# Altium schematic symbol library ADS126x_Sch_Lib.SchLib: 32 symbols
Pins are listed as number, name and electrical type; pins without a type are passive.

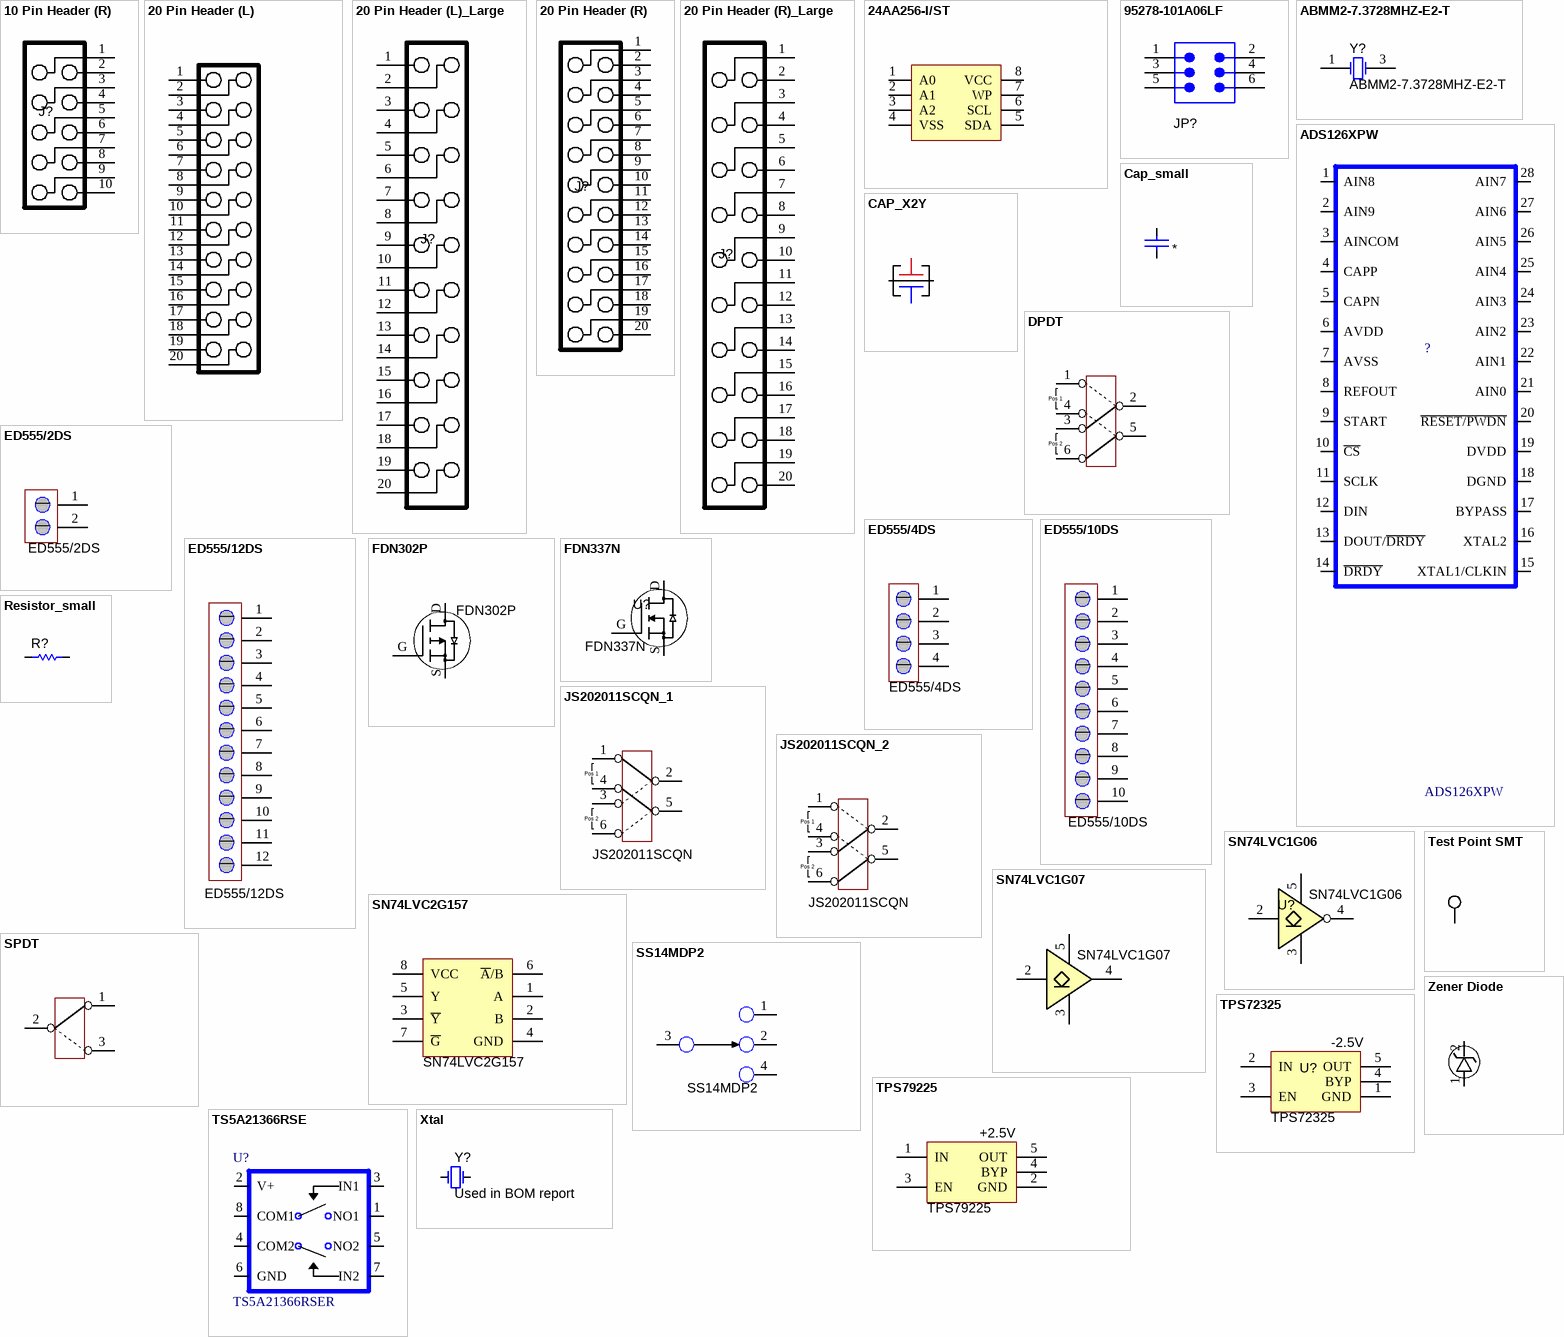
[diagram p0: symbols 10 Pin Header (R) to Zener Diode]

## 10 Pin Header (R)
designator J?, comment TSM-110-01-T-DV-P  (value not drawn)
Manufacturer: Samtec; SymbolCreator: a0282860; CompType: Used in some BOM reports.  Useful for finding later.; U/M: EA, IN, or GM
footprint HEADER_TSM-105-XX-DV_TH
pins: 1, 2, 3, 4, 5, 6, 7, 8, 9, 10

## 20 Pin Header (L)
designator J?, comment TSM-110-01-T-DV-P  (value not drawn)
Manufacturer: Samtec; SymbolCreator: a0282860; CompType: Used in some BOM reports.  Useful for finding later.; U/M: EA, IN, or GM
footprint HEADER_TSM-110-XX-DV_TH
pins: 1, 2, 3, 4, 5, 6, 7, 8, 9, 10, 11, 12, 13, 14, 15, 16, 17, 18, 19, 20

## 20 Pin Header (L)_Large
designator J?, comment TSM-110-01-T-DV-P  (value not drawn)
Manufacturer: Samtec; SymbolCreator: a0282860; CompType: Used in some BOM reports.  Useful for finding later.; U/M: EA, IN, or GM
footprint HEADER_TSM-110-XX-DV_TH
pins: 1, 2, 3, 4, 5, 6, 7, 8, 9, 10, 11, 12, 13, 14, 15, 16, 17, 18, 19, 20

## 20 Pin Header (R)
designator J?, comment TSM-110-01-T-DV-P  (value not drawn)
Manufacturer: Samtec; SymbolCreator: a0282860; CompType: Used in some BOM reports.  Useful for finding later.; U/M: EA, IN, or GM
footprint HEADER_TSM-110-XX-DV_TH
pins: 1, 2, 3, 4, 5, 6, 7, 8, 9, 10, 11, 12, 13, 14, 15, 16, 17, 18, 19, 20

## 20 Pin Header (R)_Large
designator J?, comment TSM-110-01-T-DV-P  (value not drawn)
Manufacturer: Samtec; SymbolCreator: a0282860; CompType: Used in some BOM reports.  Useful for finding later.; U/M: EA, IN, or GM
footprint HEADER_TSM-110-XX-DV_TH
pins: 1, 2, 3, 4, 5, 6, 7, 8, 9, 10, 11, 12, 13, 14, 15, 16, 17, 18, 19, 20

## 24AA256-I/ST
designator U?
IC, EEPROM, 256 kBIT, 400 kHz, 8TSSOP; Manufacturer: Microchip; SymbolCreator: a0282860; U/M: EA
pins: 1 A0, 2 A1, 3 A2, 4 VSS, 5 SDA, 6 SCL, 7 WP, 8 VCC

## 95278-101A06LF
designator JP?  (value not drawn)
Header, SMT, 100mil, 5x2; Manufacturer: FCI; U/M: EA
footprint 95278-101A06LF
pins: 1, 2, 3, 4, 5, 6

## ABMM2-7.3728MHZ-E2-T
designator Y?
Crystal, 7.3728MHz, 18pF, SMD; Manufacturer: Abracon Corportation; SymbolCreator: a0282860; U/M: EA; TaMin_C: -20; TaMax_C: 70; Frequency Stability: ±20ppm
footprint ABMM2
pins: 1 OSC1, 2 hidden, 3 OSC2, 4 hidden

## ADS126XPW
designator ?
IC, 24-bit, 38kSps A-D Converters with PGA, Internal Reference and Second ADC; MFR: TI; Second Source: C:\program files\p-cad 2004\pcad_pdf's\ADS1262_Pinout.doc; Reference: \\vette02\pmp_pcb\pcad_pdf's\ADS1262_Pinout.doc; Area: 85.53 mm
footprint PW28
pins: 1 AIN8, 2 AIN9, 3 AINCOM, 4 CAPP, 5 CAPN, 6 AVDD, 7 AVSS, 8 REFOUT, 9 START, 10 ~{CS}, 11 SCLK, 12 DIN, 13 DOUT/~{DRDY}, 14 ~{DRDY}, 15 XTAL1/CLKIN, 16 XTAL2, 17 BYPASS, 18 DGND, 19 DVDD, 20 ~{RESET/PWDN}, 21 AIN0, 22 AIN1, 23 AIN2, 24 AIN3, 25 AIN4, 26 AIN5, 27 AIN6, 28 AIN7

## Cap_small
designator C?, comment Used in BOM report  (value not drawn)
CAP, CERM, xxxF, xxV, [TempCo], xx%, [PackageReference]; SymbolCreator: a0282860; CompType: Capacitor; U/M: EA
pins: 1, 2

## CAP_X2Y
designator C?, comment Used in BOM report  (value not drawn)
CAP, CERM X2Y, [value nF], [100V], [NP0], [+/-20%], [size]; Manufacturer: Johanson Dielectrics Inc; SymbolCreator: a0282860; U/M: EA; CompType: X2Y Capacitor
pins: A, B, G, G

## DPDT
designator S?, comment CAS-220TB
SWITCH, SLIDE, DPDT, GULLWING; Manufacturer: Copal Electronics Inc; SymbolCreator: a0282860; U/M: EA
footprint DPDT PCB Mount
pins: 1, 2 C, 3, 4 6, 5, 6 2

## ED555/2DS
designator J?
Manufacturer: On Shore Technology Inc; SymbolCreator: a0282860; CompType: TERMBLOCK; U/M: EA
footprint ED555/2DS
pins: 1, 2

## ED555/4DS
designator J?
Manufacturer: On Shore Technology Inc; SymbolCreator: a0282860; CompType: TERMBLOCK; U/M: EA
pins: 1, 2, 3, 4

## ED555/10DS
designator J?
Manufacturer: On Shore Technology Inc; SymbolCreator: a0282860; CompType: TERMBLOCK; U/M: EA
footprint ED555/10DS
pins: 1, 2, 3, 4, 5, 6, 7, 8, 9, 10

## ED555/12DS
designator J?
Manufacturer: On Shore Technology Inc; SymbolCreator: a0282860; CompType: TERMBLOCK; U/M: EA
pins: 1, 2, 3, 4, 5, 6, 7, 8, 9, 10, 11, 12

## FDN302P
designator U?
Manufacturer: Fairchild Semiconductor; SymbolCreator: a0282860; CompType: Used in some BOM reports.  Useful for finding later.; U/M: EA
footprint SOT-23
pins: D, G, S

## FDN337N
designator U?
Manufacturer: Fairchild Semiconductor; SymbolCreator: a0282860; CompType: Used in some BOM reports.  Useful for finding later.; U/M: EA
footprint SOT-23
pins: D, G, S

## JS202011SCQN_1
designator S?, comment JS202011SCQN
Manufacturer: C&K Components; SymbolCreator: a0282860; CompType: Used in some BOM reports.  Useful for finding later.; U/M: EA
footprint DPDT- old
pins: 1, 2 C, 3, 4 6, 5, 6 2

## JS202011SCQN_2
designator S?, comment JS202011SCQN
Manufacturer: C&K Components; SymbolCreator: a0282860; CompType: Used in some BOM reports.  Useful for finding later.; U/M: EA
footprint DPDT- old
pins: 1, 2 C, 3, 4 6, 5, 6 2

## Resistor_small
designator R?, comment Used in BOM report  (value not drawn)
RES, xxx ohm, x%, xW, [PackageReference]; CompType: Resistor; U/M: EA
signal-integrity model Resistor
simulation model Resistor
footprint TBD
footprint 0201
footprint 0402
footprint 0603
footprint 0603_HV
footprint 0805
footprint 0805_HV
footprint 1206
footprint 1210
footprint 1812
footprint 2010
footprint 2512
pins: 1, 2

## SN74LVC1G06
designator U?
Manufacturer: Texas Instruments; SymbolCreator: Use LDAP id; CompType: Used in some BOM reports.  Useful for finding later.; U/M: EA
footprint DBV-5
footprint DCK-5
pins: 1 N.C. hidden, 2 A, 3 GND, 4 Y, 5 VCC

## SN74LVC1G07
designator U?
Manufacturer: Texas Instruments; SymbolCreator: Use LDAP id; CompType: Used in some BOM reports.  Useful for finding later.; U/M: EA
footprint DBV-5
footprint DCK-5
pins: 1 N.C. hidden, 2 A, 3 GND, 4 Y, 5 VCC

## SN74LVC2G157
designator U?
Single, 2-Line to 1 Data Selector/Multiplexer; Manufacturer: Texas Instruments; SymbolCreator: a0282860; CompType: Used in some BOM reports.  Useful for finding later.; U/M: EA
footprint DCT-8
footprint DCU-8
pins: 1 A, 2 B, 3 ~{Y}, 4 GND, 5 Y, 6 ~{A}/B, 7 ~{G}, 8 VCC

## SPDT
designator S?, comment CAS-120TB
SWITCH, SLIDE, SPDT, GULLWING; Manufacturer: Copal Electronics Inc; SymbolCreator: a0282860; U/M: EA
footprint SPDT PCB Mount
pins: 1, 2 C, 3

## SS14MDP2
designator S?
SW SLIDE ULTRA MINI SP3T TOP ACT; Manufacturer: NKK Switches; SymbolVersion: 20012-6-13; SymbolCreator: a0282860; CompType: Used in some BOM reports.  Useful for finding later.; U/M: EA
pins: 1, 2, 3 COM, 4 3

## Test Point SMT
designator TP?, comment 5015  (value not drawn)
TEST POINT, MINIATURE, SMT; Manufacturer: Keystone Electronics; SymbolCreator: a0282860; U/M: EA
footprint 5015
pins: 1

## TPS72325
designator U?  Vout: -2.5V  (hidden comment: TPS72325)
Manufacturer: Texas Instruments; SymbolCreator: a0282860; CompType: Used in some BOM reports.  Useful for finding later.; U/M: EA
footprint DBV-5
pins: 1 GND, 2 IN, 3 EN, 4 BYP, 5 OUT

## TPS79225
designator U?  Vout: +2.5V  (hidden comment: TPS79225)
Manufacturer: Texas Instruments; SymbolCreator: a0282860; CompType: Used in some BOM reports.  Useful for finding later.; U/M: EA, IN, or GM
footprint DBV-5
pins: 1 IN, 2 GND, 3 EN, 4 BYP, 5 OUT

## TS5A21366RSE
designator U?, comment TS5A21366RSER
IC, Single-Channel 10 Ohms SPDT Analog Switch with enable; Manufacturer: TI; Alternate Manufacturer: None; Area: 6.25 mm
footprint RSE-8
pins: 1 NO1, 2 V+, 3 IN1, 4 COM2, 5 NO2, 6 GND, 7 IN2, 8 COM1

## Xtal
designator Y?, comment Used in BOM report
Crystal, xxxMHz, xxpF, [MountType]; U/M: EA
simulation model XTAL (Altium default crystal oscillator model)
pins: 1 OSC1, 2 OSC2

## Zener Diode
designator D?, comment DDZ6V2B-7
DIODE, ZENER, 6.2V, 500mW, SOD-123; Manufacturer: Diodes Inc; SymbolCreator: a0282860; CompType: Zener Diode; U/M: EA
footprint SOD-123
pins: 1 Anode, 2 Cathode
